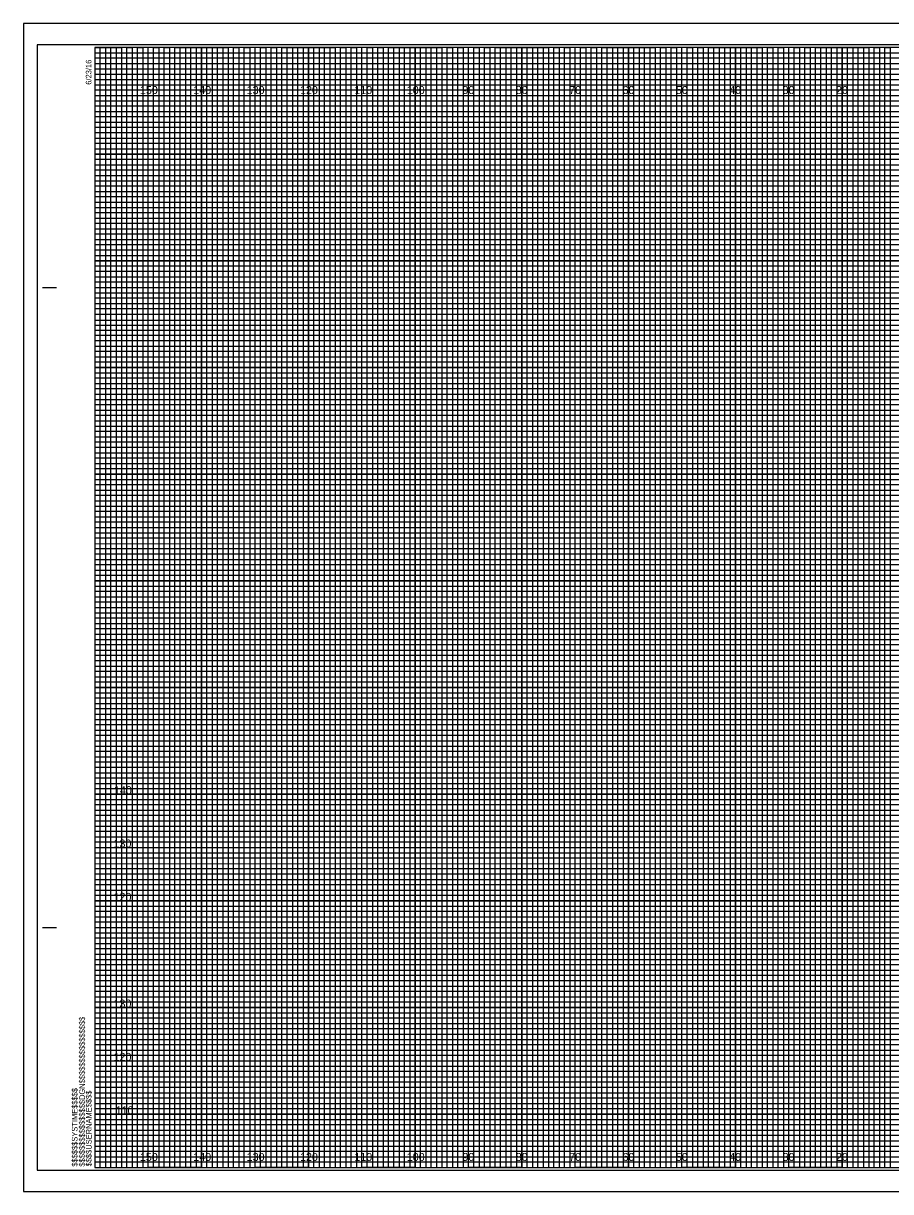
# Model space of a CAD drawing. Extents: x -13 to 323, y -5 to 215.
# Drawn here: x -13.4 to 149.1, y -4.5 to 214.5 of the extents above; entities that cross this region are included whole.
import ezdxf

# ---------------------------------------------------------------- set-up
doc = ezdxf.new("R2010")
doc.units = 0
for name, color, linetype in [('Exist Cross Section Cell', 7, 'Continuous'), ('Prop XS Elevation Labels', 7, 'Continuous'), ('Sheet Cross Section CELL', 7, 'Continuous'), ('Sheet Cross Section Grid Major CELL', 7, 'Continuous'), ('Sheet Cross Section Grid Middle CELL', 7, 'Continuous'), ('Sheet Cross Section Grid Minor 1 CELL', 7, 'Continuous'), ('Sheet Cross Section Grid Minor 2 CELL', 7, 'Continuous'), ('Sheet Cutting Line CELL', 7, 'Continuous'), ('Sheet DOT Grid CELL', 7, 'Continuous'), ('Sheet Plot Border Inside CELL', 7, 'Continuous'), ('Sheet Plot Border Outside CELL', 7, 'Continuous')]:
    doc.layers.add(name, color=color, linetype=linetype)

msp = doc.modelspace()

# ---------------------------------------------------------------- linework, layer by layer
at = {"layer": 'Sheet Cross Section CELL'}
for p, q in [((-9.8, 165), (-7.3, 165)), ((-9.7, 165), (-7.2, 165)), ((-9.8, 45), (-7.3, 45)), ((-9.7, 45), (-7.2, 45)), ((0, 0), (0, 0)), ((0, 0), (0, 0)), ((0, 0), (0, 0)), ((0, 0), (0, 0)), ((0, 0), (0, 0)), ((0, 0), (0, 0)), ((0, 0), (0, 0))]:
    msp.add_line(p, q, dxfattribs=at)
msp.add_lwpolyline([(320, 210), (0, 210), (0, 0), (320, 0)], close=True, dxfattribs=at)
at = {"layer": 'Sheet Cross Section Grid Major CELL'}
for p, q in [((10, 210), (0, 210)), ((10, 0), (10, 210)), ((30, 210), (20, 210)), ((20, 210), (20, 0)), ((30, 0), (30, 210)), ((50, 210), (40, 210)), ((40, 210), (40, 0)), ((50, 0), (50, 210)), ((70, 210), (60, 210)), ((60, 210), (60, 0)), ((70, 0), (70, 210)), ((90, 210), (80, 210)), ((80, 210), (80, 0)), ((90, 0), (90, 210)), ((110, 210), (100, 210)), ((100, 210), (100, 0)), ((110, 0), (110, 210)), ((130, 210), (120, 210)), ((120, 210), (120, 0)), ((130, 0), (130, 210)), ((150, 210), (140, 210)), ((140, 210), (140, 0)), ((20, 0), (10, 0)), ((40, 0), (30, 0)), ((60, 0), (50, 0)), ((80, 0), (70, 0)), ((100, 0), (90, 0)), ((120, 0), (110, 0)), ((140, 0), (130, 0))]:
    msp.add_line(p, q, dxfattribs=at)
for points in [[(0, 200), (320, 200), (320, 190), (0, 190)], [(0, 180), (320, 180), (320, 170), (0, 170)], [(0, 160), (320, 160), (320, 150), (0, 150)], [(0, 140), (320, 140), (320, 130), (0, 130)], [(0, 120), (320, 120), (320, 110), (0, 110)], [(0, 100), (320, 100), (320, 90), (0, 90)], [(0, 80), (320, 80), (320, 70), (0, 70)], [(0, 60), (320, 60), (320, 50), (0, 50)], [(0, 40), (320, 40), (320, 30), (0, 30)], [(0, 20), (320, 20), (320, 10), (0, 10)]]:
    msp.add_lwpolyline(points, dxfattribs=at)
at = {"layer": 'Sheet Cross Section Grid Middle CELL'}
for points in [[(0, 210), (5, 210), (5, 0), (15, 0), (15, 210), (25, 210), (25, 0), (35, 0), (35, 210), (45, 210), (45, 0), (55, 0), (55, 210), (65, 210), (65, 0), (75, 0), (75, 210), (85, 210), (85, 0), (95, 0), (95, 210), (105, 210), (105, 0), (115, 0), (115, 210), (125, 210), (125, 0), (135, 0), (135, 210), (145, 210), (145, 0), (155, 0)], [(0, 205), (275, 205)], [(0, 185), (320, 185), (320, 195), (0, 195)], [(0, 165), (320, 165), (320, 175), (0, 175)], [(0, 145), (320, 145), (320, 155), (0, 155)], [(0, 125), (320, 125), (320, 135), (0, 135)], [(0, 105), (320, 105), (320, 115), (0, 115)], [(0, 85), (320, 85), (320, 95), (0, 95)], [(0, 65), (320, 65), (320, 75), (0, 75)], [(0, 45), (320, 45), (320, 55), (0, 55)], [(0, 25), (320, 25), (320, 35), (0, 35)], [(0, 5), (320, 5), (320, 15), (0, 15)]]:
    msp.add_lwpolyline(points, dxfattribs=at)
at = {"layer": 'Sheet Cross Section Grid Minor 1 CELL'}
for p, q in [((0, 209), (260, 209)), ((260, 207.98), (0, 207.98)), ((0, 207.98), (0, 207)), ((0, 207), (260, 207)), ((260, 205.89), (0, 205.89)), ((0, 205.89), (0, 204)), ((0, 204), (320, 204))]:
    msp.add_line(p, q, dxfattribs=at)
for points in [[(0, 203), (270, 203), (320, 203), (320, 202), (0, 202)], [(0, 201), (320, 201), (320, 199), (0, 199)], [(0, 198), (320, 198), (320, 197), (0, 196.98)], [(0, 196), (320, 196), (320, 194), (0, 194)], [(0, 193), (320, 193), (320, 192), (0, 192)], [(0, 191), (320, 191), (320, 189), (0, 189)], [(0, 188), (320, 188), (320, 187), (0, 187)], [(0, 186), (320, 186), (320, 184), (0, 184)], [(0, 183), (320, 183), (320, 182), (0, 182)], [(0, 181), (320, 181), (320, 179), (0, 179)], [(0, 178), (320, 178), (320, 177), (0, 177)], [(0, 176), (320, 176), (320, 173.95), (320, 173), (320, 172), (0, 172)], [(0, 174), (320, 174), (320, 173), (0, 173)], [(0, 171), (320, 171), (320, 169), (0, 169.03)], [(0, 169.03), (320, 169), (320, 168), (0, 168)], [(0, 167), (320, 167), (320, 166), (0, 166)], [(0, 164), (320, 164), (320, 163), (0, 163)], [(0, 162), (320, 162), (320, 161), (0, 161)], [(-0.07, 158.89), (320, 158.89), (320, 157.88), (-0.07, 157.88)], [(0, 157), (320, 157), (320, 156), (0, 156)], [(0, 154), (320, 154), (320, 153), (0, 153)], [(0, 152), (320, 152), (320, 151), (0, 151)], [(0, 149), (320, 149), (320, 148), (0, 148)], [(0, 147), (320, 147), (320, 146), (0, 146)], [(0, 144), (320, 144), (320, 143), (0, 143)], [(0, 142), (320, 142), (320, 141), (0, 141)], [(0, 139), (320, 139), (319.99, 137.98), (0, 138)], [(0, 137), (320, 137), (320, 136), (0, 136)], [(0, 134), (320, 134), (320, 133), (0, 133)], [(0, 132), (320, 132), (320, 131), (0, 131)], [(0, 129), (320, 129), (320, 128), (0, 128)], [(0, 127), (320, 127), (320, 126), (0, 126)], [(0, 124), (320, 124), (320, 123), (0, 123)], [(0, 122), (320, 122), (320, 121), (0, 121)], [(0, 119), (320, 119), (320, 118), (0, 118)], [(0, 116.99), (320.07, 116.91), (320, 116), (0, 116)], [(0, 114), (320, 114), (320, 113), (0, 113)], [(0, 112), (320, 112), (320, 111), (0, 111)], [(0, 109), (320, 109), (320, 108), (0, 108)], [(0, 107), (320, 107), (320, 106), (0, 106)], [(0, 104), (320, 104), (320, 103), (0, 103)], [(0, 102), (320, 102), (320, 101), (0, 101)], [(0, 99), (320, 99), (320, 98), (0, 98)], [(0, 97), (320, 97), (320, 96), (0, 96)], [(0, 94), (320, 94), (320, 93), (0, 93)], [(0, 92), (320, 92), (320, 91), (0, 91)], [(0, 89), (320, 89), (320, 88), (0, 88)], [(0, 87), (320, 87), (320, 86), (0, 86)], [(0, 84), (320, 84), (320, 83), (0, 83)], [(0, 82), (320, 82), (320, 81), (0, 81)], [(0, 79), (320, 79), (319.99, 77.98), (0, 78)], [(0, 77), (320, 77), (320, 76), (0, 76)], [(0, 74), (320, 74), (320, 73), (0, 73)], [(0, 72), (320, 72), (320, 71), (0, 71)], [(0, 69), (320, 69), (320, 68), (0, 68)], [(0, 67), (320, 67), (320, 66), (0, 66)], [(0, 64), (320, 64), (320, 63), (0, 63)], [(0, 62), (320, 62), (320, 61), (0, 61)], [(0, 59), (320, 59), (320, 58), (0, 58)], [(0, 56.99), (320.07, 56.91), (320, 56), (0, 56)], [(0, 54), (320, 54), (320, 53), (0, 53)], [(0, 52), (320, 52), (320, 51), (0, 51)], [(0, 49), (320, 49), (320, 48), (0, 48)], [(0, 47), (320, 47), (320, 46), (0, 46)], [(0, 44), (320, 44), (320, 43), (0, 43)], [(0, 42), (320, 42), (320, 41), (0, 41)], [(0, 39), (320, 39), (320, 38), (0, 38)], [(0, 37), (320, 37), (320, 36), (0, 36)], [(0, 34), (320, 34), (320, 33), (0, 33)], [(0, 32), (320, 32), (320, 31), (0, 31)], [(0, 29), (320, 29), (320, 28), (0, 28)], [(0, 27), (320, 27), (320, 26), (0, 26)], [(0, 24), (320, 24), (320, 23), (0, 23)], [(0, 22), (320, 22), (320, 21), (0, 21)], [(0, 19), (320, 19), (320, 18), (0, 18)], [(0, 17), (320, 17), (320, 16), (0, 16)], [(0, 14), (320, 14), (320, 13), (0, 13)], [(0, 12), (320, 12), (320, 11), (0, 11)], [(0, 9), (320, 9), (320, 8), (0, 8)], [(0, 7), (320, 7), (320, 6), (0, 6)], [(0, 4), (320, 4), (320, 3), (0, 3)], [(0, 2), (320, 2), (320, 1), (0, 1)]]:
    msp.add_lwpolyline(points, dxfattribs=at)
at = {"layer": 'Sheet Cross Section Grid Minor 2 CELL'}
for points in [[(0, 0), (1, 0), (1, 210), (2, 210), (2, 0)], [(2, 0), (3, 0), (3, 210), (4, 210), (4, 0)], [(5, 0), (6, 0), (6, 210), (7, 210), (7, 0)], [(7, 0), (8, 0), (8, 210), (9, 210), (9, 0)], [(10, 0), (11, 0), (11, 210), (12, 210), (12, 0)], [(12, 0), (13, 0), (13, 210), (14, 210), (14, 0)], [(15, 0), (16, 0), (16, 210), (17, 210), (17, 0)], [(17, 0), (18, 0), (18, 210), (19, 210), (19, 0)], [(20, 0), (21, 0), (21, 210), (22, 210), (22, 0)], [(22, 0), (23, 0), (23, 210), (24, 210), (24, 0)], [(25, 0), (26, 0), (26, 210), (27, 210), (27, 0)], [(27, 0), (28, 0), (28, 210), (29, 210), (29, 0)], [(30, 0), (31, 0), (31, 210), (32, 210), (32, 0)], [(32, 0), (33, 0), (33, 210), (34, 210), (34, 0)], [(35, 0), (36, 0), (36, 210), (37, 210), (37, 0)], [(37, 0), (38, 0), (38, 210), (39, 210), (39, 0)], [(40, 0), (41, 0), (41, 210), (42, 210), (42, 0)], [(42, 0), (43, 0), (43, 210), (44, 210), (44, 0)], [(45, 0), (46, 0), (46, 210), (47, 210), (47, 0)], [(47, 0), (48, 0), (48, 210), (49, 210), (49, 0)], [(50, 0), (51, 0), (51, 210), (52, 210), (52, 0)], [(52, 0), (53, 0), (53, 210), (54, 210), (54, 0)], [(55, 0), (56, 0), (56, 210), (57, 210), (57, 0)], [(57, 0), (58, 0), (58, 210), (59, 210), (59, 0)], [(60, 0), (61, 0), (61, 210), (62, 210), (62, 0)], [(62, 0), (63, 0), (63, 210), (64, 210), (64, 0)], [(65, 0), (66, 0), (66, 210), (67, 210), (67, 0)], [(67, 0), (68, 0), (68, 210), (69, 210), (69, 0)], [(70, 0), (71, 0), (71, 210), (72, 210), (72, 0)], [(72, 0), (73, 0), (73, 210), (74, 210), (74, 0)], [(75, 0), (76, 0), (76, 210), (77, 210), (77, 0)], [(77, 0), (78, 0), (78, 210), (79, 210), (79, 0)], [(80, 0), (81, 0), (81, 210), (82, 210), (82, 0)], [(82, 0), (83, 0), (83, 210), (84, 210), (84, 0)], [(85, 0), (86, 0), (86, 210), (87, 210), (87, 0)], [(87, 0), (88, 0), (88, 210), (89, 210), (89, 0)], [(90, 0), (91, 0), (91, 210), (92, 210), (92, 0)], [(92, 0), (93, 0), (93, 210), (94, 210), (94, 0)], [(95, 0), (96, 0), (96, 210), (97, 210), (97, 0)], [(97, 0), (98, 0), (98, 210), (99, 210), (99, 0)], [(100, 0), (101, 0), (101, 210), (102, 210), (102, 0)], [(102, 0), (103, 0), (103, 210), (104, 210), (104, 0)], [(105, 0), (106, 0), (106, 210), (107, 210), (107, 0)], [(107, 0), (108, 0), (108, 210), (109, 210), (109, 0)], [(110, 0), (111, 0), (111, 210), (112, 210), (112, 0)], [(112, 0), (113, 0), (113, 210), (114, 210), (114, 0)], [(115, 0), (116, 0), (116, 210), (117, 210), (117, 0)], [(117, 0), (118, 0), (118, 210), (119, 210), (119, 0)], [(120, 0), (121, 0), (121, 210), (122, 210), (122, 0)], [(122, 0), (123, 0), (123, 210), (124, 210), (124, 0)], [(125, 0), (126, 0), (126, 210), (127, 210), (127, 0)], [(127, 0), (128, 0), (128, 210), (129, 210), (129, 0)], [(130, 0), (131, 0), (131, 210), (132, 210), (132, 0)], [(132, 0), (133, 0), (133, 210), (134, 210), (134, 0)], [(135, 0), (136, 0), (136, 210), (137, 210), (137, 0)], [(137, 0), (138, 0), (138, 210), (139, 210), (139, 0)], [(140, 0), (141, 0), (141, 210), (142, 210), (142, 0)], [(142, 0), (143, 0), (143, 210), (144, 210), (144, 0)], [(145, 0), (146, 0), (146, 210), (147, 210), (147, 0)], [(147, 0), (148, 0), (148, 210), (149, 210), (149, 0)]]:
    msp.add_lwpolyline(points, dxfattribs=at)
at = {"layer": 'Sheet Cutting Line CELL'}
for p, q in [((323.3, 214.5), (-13.4, 214.5)), ((-13.4, 214.5), (-13.4, -4.5)), ((-13.4, -4.5), (323.3, -4.5))]:
    msp.add_line(p, q, dxfattribs=at)
at = {"layer": 'Sheet DOT Grid CELL'}
for p, q in [((10, 0), (10, 210)), ((20, 0), (20, 210)), ((30, 0), (30, 210)), ((40, 0), (40, 210)), ((50, 0), (50, 210)), ((60, 0), (60, 210)), ((70, 0), (70, 210)), ((80, 0), (80, 210)), ((90, 0), (90, 210)), ((100, 0), (100, 210)), ((110, 0), (110, 210)), ((120, 0), (120, 210)), ((130, 0), (130, 210)), ((140, 0), (140, 210)), ((0, 200), (320, 200)), ((0, 190), (320, 190)), ((0, 180), (320, 180)), ((0, 170), (320, 170)), ((0, 160), (320, 160)), ((0, 150), (320, 150)), ((0, 140), (320, 140)), ((0, 130), (320, 130)), ((0, 120), (320, 120)), ((0, 110), (320, 110)), ((0, 100), (320, 100)), ((0, 90), (320, 90)), ((0, 80), (320, 80)), ((0, 70), (320, 70)), ((0, 60), (320, 60)), ((0, 50), (320, 50)), ((0, 40), (320, 40)), ((0, 30), (320, 30)), ((0, 20), (320, 20)), ((0, 10), (320, 10))]:
    msp.add_line(p, q, dxfattribs=at)
at = {"layer": 'Sheet Plot Border Inside CELL'}
msp.add_lwpolyline([(-10.8, -0.5), (322.4, -0.5), (322.4, 210.5), (-10.8, 210.5)], close=True, dxfattribs=at)
at = {"layer": 'Sheet Plot Border Outside CELL'}
msp.add_lwpolyline([(-13.4, -4.5), (323.3, -4.5), (323.3, 214.5), (-13.4, 214.5)], close=True, dxfattribs=at)

# ---------------------------------------------------------------- texts
at = {"layer": 'Exist Cross Section Cell'}
for s, p in [('150', (8.44, 201.25)), ('140', (18.44, 201.25)), ('130', (28.44, 201.25)), ('120', (38.44, 201.25)), ('110', (48.62, 201.25)), ('100', (58.44, 201.25)), ('90', (68.86, 201.25)), ('80', (78.86, 201.25)), ('70', (88.86, 201.25)), ('60', (98.86, 201.25)), ('50', (108.86, 201.25)), ('40', (118.86, 201.25)), ('30', (128.86, 201.25)), ('20', (138.86, 201.25)), ('150', (8.44, 1.25)), ('140', (18.44, 1.25)), ('130', (28.44, 1.25)), ('120', (38.44, 1.25)), ('110', (48.62, 1.25)), ('100', (58.44, 1.25)), ('90', (68.86, 1.25)), ('80', (78.86, 1.25)), ('70', (88.86, 1.25)), ('60', (98.86, 1.25)), ('50', (108.86, 1.25)), ('40', (118.86, 1.25)), ('30', (128.86, 1.25)), ('20', (138.86, 1.25))]:
    msp.add_text(s, height=1.5, dxfattribs=at).set_placement(p)
at = {"layer": 'Prop XS Elevation Labels'}
for s, p in [('140', (3.57, 70)), ('130', (3.49, 60)), ('120', (3.5, 50)), ('130', (3.49, 30)), ('120', (3.5, 20)), ('110', (3.88, 10))]:
    msp.add_text(s, height=1.5, dxfattribs=at).set_placement(p)
at = {"layer": 'Sheet Cross Section CELL'}
for s, p in [('6/23/16', (-0.65, 203)), ('$$$$$$$$$$$$$$$$DGN$$$$$$$$$$$$$$$$', (-1.88, 0.18)), ('$$$$$$SYSTIME$$$$$', (-3.26, 0.18)), ('$$$$USERNAME$$$$', (-0.62, 0.23))]:
    msp.add_text(s, height=1.05, rotation=90, dxfattribs=at).set_placement(p)

doc.saveas('drawing.dxf')
